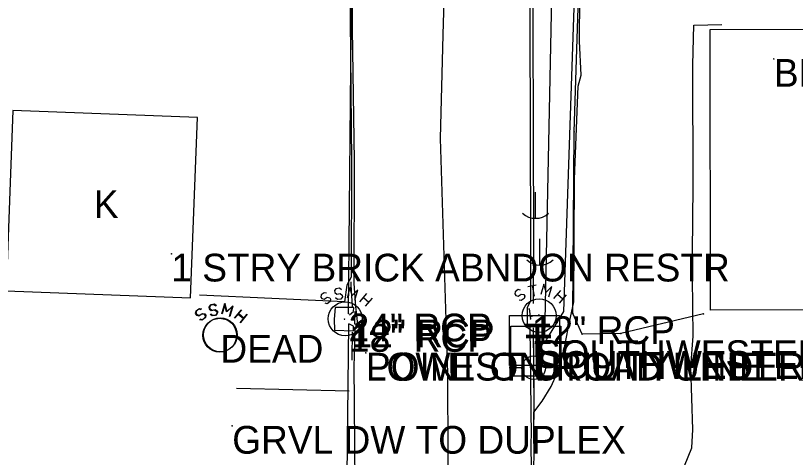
# Model space of a CAD drawing. Extents: x 1304270 to 1306561, y 1876019 to 1876752.
# Drawn here: x 1304900.2 to 1305040.8, y 1876244.8 to 1876324.4 of the extents above; entities that cross this region are included whole.
import ezdxf

# ---------------------------------------------------------------- set-up
doc = ezdxf.new("R2010")
doc.units = 0
for name, color, linetype in [('S_BUILDING', 7, 'Continuous'), ('S_BUILDING_ANNOT', 7, 'Continuous'), ('S_CATCH_BASIN', 7, 'Continuous'), ('S_CURB', 7, 'Continuous'), ('S_DRG_PT_SYM', 7, 'Continuous'), ('S_DRIVEWAY', 7, 'Continuous'), ('S_EDGE_CONCRETE', 7, 'Continuous'), ('S_EDGE_PAVEMENT', 7, 'Continuous'), ('S_ELECTRIC_UTILITIES_ANNOT', 7, 'Continuous'), ('S_FIBER_OPTIC_CABLE', 7, 'Continuous'), ('S_GAS_UTILITIES', 7, 'Continuous'), ('S_MSC_PT_SYM', 7, 'Continuous'), ('S_PARKING', 7, 'Continuous'), ('S_PAVEMENT_CROWN', 7, 'Continuous'), ('S_SANITARY_SEWER', 7, 'Continuous'), ('S_SANITARY_SEWER_ANNOT', 7, 'Continuous'), ('S_STORM_SEWER', 7, 'Continuous'), ('S_STORM_SEWER_ANNOT', 7, 'Continuous'), ('S_STR_PT_SYM', 7, 'Continuous'), ('S_SURVEY_TEXT_ANNOT', 7, 'Continuous'), ('S_TELEPHONE_UTILITIES', 7, 'Continuous'), ('S_TELEPHONE_UTILITIES_ANNOT', 7, 'Continuous'), ('S_UTILITY_POLE', 7, 'Continuous'), ('S_UTL_PT_SYM', 7, 'Continuous')]:
    doc.layers.add(name, color=color, linetype=linetype)

msp = doc.modelspace()

# ---------------------------------------------------------------- linework, layer by layer
at = {"layer": 'S_BUILDING'}
for points in [[(1305105.68, 1876271.43), (1305025.53, 1876271.29), (1305025.44, 1876321.83), (1305105.6, 1876321.96)], [(1304933.02, 1876306.02), (1304899.75, 1876307.28), (1304898.52, 1876274.75), (1304931.79, 1876273.49)]]:
    msp.add_lwpolyline(points, close=True, dxfattribs=at)
at = {"layer": 'S_CATCH_BASIN'}
for p, q in [((1304992.86, 1876271.51), (1304993.07, 1876269.69)), ((1304961.43, 1876268.81), (1304961.47, 1876270.98))]:
    msp.add_line(p, q, dxfattribs=at)
at = {"layer": 'S_CURB'}
for points in [[(1305002.33, 1876389.51), (1305000.99, 1876388.54), (1305000.03, 1876387.77), (1304998.78, 1876386.42), (1304997.67, 1876385.02), (1304996.71, 1876383.64), (1304995.81, 1876382.15), (1304995.25, 1876381.09), (1304994.76, 1876379.59), (1304994.22, 1876377.46), (1304993.74, 1876375.44), (1304993.56, 1876373.88), (1304993.51, 1876373.22), (1304993.31, 1876353.04), (1304993.41, 1876337.87), (1304993.52, 1876322.71), (1304993.56, 1876303.33), (1304993.6, 1876283.94), (1304993.53, 1876272.49)], [(1304960.7, 1876276.37), (1304960.7, 1876275.85), (1304960.93, 1876271.96)], [(1304960.9, 1876267.34), (1304960.85, 1876262.73), (1304960.87, 1876262.27)], [(1304993.57, 1876268.11), (1304993.67, 1876253.6), (1304993.62, 1876249.39)]]:
    msp.add_lwpolyline(points, dxfattribs=at)
at = {"layer": 'S_DRG_PT_SYM'}
for points in [[(1304992.86, 1876271.51), (1304992.86, 1876271.56), (1304992.86, 1876271.51), (1304992.81, 1876271.51), (1304992.86, 1876271.51), (1304992.86, 1876271.46), (1304992.86, 1876271.51), (1304992.91, 1876271.51)], [(1304961.47, 1876270.98), (1304961.47, 1876271.03), (1304961.47, 1876270.98), (1304961.42, 1876270.98), (1304961.47, 1876270.98), (1304961.47, 1876270.93), (1304961.47, 1876270.98), (1304961.52, 1876270.98)], [(1304961.43, 1876268.81), (1304961.43, 1876268.86), (1304961.43, 1876268.81), (1304961.38, 1876268.81), (1304961.43, 1876268.81), (1304961.43, 1876268.76), (1304961.43, 1876268.81), (1304961.48, 1876268.81)], [(1304993.07, 1876269.69), (1304993.07, 1876269.74), (1304993.07, 1876269.69), (1304993.02, 1876269.69), (1304993.07, 1876269.69), (1304993.07, 1876269.64), (1304993.07, 1876269.69), (1304993.12, 1876269.69)]]:
    msp.add_lwpolyline(points, dxfattribs=at)
at = {"layer": 'S_DRIVEWAY'}
msp.add_lwpolyline([(1304940.08, 1876257.24), (1304960.4, 1876256.74)], dxfattribs=at)
at = {"layer": 'S_EDGE_CONCRETE'}
for points in [[(1304961.23, 1876271.74), (1304957.86, 1876271.78), (1304957.69, 1876269.66), (1304957.73, 1876267.7), (1304961.17, 1876267.53), (1304961.14, 1876268.37), (1304960.3, 1876268.83)], [(1304960.46, 1876270.43), (1304961.16, 1876271.02), (1304961.23, 1876271.74)]]:
    msp.add_lwpolyline(points, dxfattribs=at)
at = {"layer": 'S_EDGE_PAVEMENT'}
for points in [[(1304992.58, 1876395.95), (1304992.67, 1876392.97), (1304992.89, 1876387.96), (1304993.12, 1876382.52), (1304992.95, 1876377.14), (1304992.83, 1876373.03), (1304992.83, 1876353.07), (1304992.88, 1876337.99), (1304992.93, 1876322.91), (1304993, 1876303.41), (1304993.07, 1876283.92), (1304993.07, 1876272.99), (1304992.49, 1876271.71), (1304992.46, 1876268.84), (1304992.98, 1876268.15), (1304993.15, 1876253.51), (1304993.2, 1876248.53), (1304993.13, 1876247.77), (1304993.23, 1876236.09), (1304993.14, 1876235.17), (1304993.16, 1876210.69)], [(1304961.3, 1876394.03), (1304961.33, 1876382.17), (1304961.23, 1876375.71), (1304961.22, 1876372.29), (1304960.99, 1876349.53), (1304961.06, 1876339.46), (1304960.95, 1876322), (1304961.28, 1876298.1), (1304961.25, 1876276.13), (1304961.53, 1876271.86), (1304961.62, 1876270.95), (1304961.87, 1876268.65), (1304961.43, 1876268.03), (1304961.3, 1876262.61), (1304961.21, 1876261.58), (1304961.4, 1876239.81), (1304961.49, 1876224.87), (1304961.47, 1876212.95)], [(1304993.51, 1876235.7), (1304993.73, 1876245.32), (1304993.66, 1876249.1), (1304993.69, 1876252.91), (1304995.2, 1876254.9), (1304996.77, 1876257.52), (1304997.79, 1876259.79), (1304999.07, 1876263.98), (1304999.95, 1876268.25), (1305000.86, 1876272.77), (1305001.03, 1876294.9), (1305001.64, 1876311.63), (1305002.2, 1876313.63), (1305001.91, 1876319.75), (1305001.96, 1876327.81)], [(1304994.06, 1876235.43), (1304999.1, 1876235.6), (1305007.63, 1876235.79), (1305013.63, 1876236.11), (1305016.38, 1876236.91), (1305020.82, 1876243.26), (1305022.14, 1876246.48), (1305022.34, 1876249.8), (1305021.98, 1876261.06), (1305022.37, 1876266.57), (1305022.29, 1876277.18), (1305022.28, 1876281.63), (1305022.38, 1876293.68), (1305022.35, 1876315.48), (1305022.51, 1876322.64), (1305027.56, 1876322.77)]]:
    msp.add_lwpolyline(points, dxfattribs=at)
at = {"layer": 'S_FIBER_OPTIC_CABLE'}
for p, q in [((1305001.98, 1876356.98), (1304999.02, 1876271.02)), ((1304997.12, 1876341.23), (1304995.58, 1876266.56)), ((1304999.02, 1876271.02), (1304995.98, 1876266.07))]:
    msp.add_line(p, q, dxfattribs=at)
at = {"layer": 'S_GAS_UTILITIES'}
for p, q in [((1305000.96, 1876303.41), (1305001.91, 1876334.61)), ((1305000.68, 1876270.67), (1305000.96, 1876303.41)), ((1305002.36, 1876266.93), (1305000.68, 1876270.67)), ((1305024.24, 1876270.6), (1305009.34, 1876267.08)), ((1305009.34, 1876267.08), (1305002.36, 1876266.93))]:
    msp.add_line(p, q, dxfattribs=at)
at = {"layer": 'S_MSC_PT_SYM'}
for points in [[(1304963.4, 1876263.6), (1304963.4, 1876263.65), (1304963.4, 1876263.6), (1304963.35, 1876263.6), (1304963.4, 1876263.6), (1304963.4, 1876263.55), (1304963.4, 1876263.6), (1304963.45, 1876263.6)], [(1304939.3, 1876250.42), (1304939.3, 1876250.47), (1304939.3, 1876250.42), (1304939.25, 1876250.42), (1304939.3, 1876250.42), (1304939.3, 1876250.37), (1304939.3, 1876250.42), (1304939.35, 1876250.42)]]:
    msp.add_lwpolyline(points, dxfattribs=at)
at = {"layer": 'S_PARKING'}
msp.add_lwpolyline([(1304960.55, 1876338.03), (1304960.57, 1876323.7), (1304960.68, 1876310.86), (1304960.8, 1876298.03), (1304960.72, 1876277.25), (1304959.98, 1876275.76), (1304959.52, 1876272.78), (1304946.45, 1876273.4), (1304933.38, 1876274.01)], dxfattribs=at)
at = {"layer": 'S_PAVEMENT_CROWN'}
msp.add_lwpolyline([(1304978.68, 1876396.09), (1304977.75, 1876372.31), (1304977.76, 1876355.96), (1304977.78, 1876339.61), (1304977.29, 1876320.92), (1304976.79, 1876302.23), (1304977.44, 1876281.07), (1304978.08, 1876259.92), (1304978.16, 1876244.79), (1304978.24, 1876229.66), (1304977.14, 1876211.47)], dxfattribs=at)
at = {"layer": 'S_SANITARY_SEWER'}
for p, q in [((1304955.88, 1876274.42), (1304955.34, 1876274.03)), ((1304956.31, 1876274.34), (1304955.88, 1876274.42)), ((1304962.31, 1876272.79), (1304963.55, 1876274.26)), ((1304955.34, 1876274.03), (1304955.26, 1876273.64)), ((1304955.26, 1876273.64), (1304955.45, 1876273.37)), ((1304955.45, 1876273.37), (1304955.88, 1876273.25)), ((1304955.88, 1876273.25), (1304956.42, 1876273.6)), ((1304956.42, 1876273.6), (1304956.89, 1876273.53)), ((1304956.97, 1876272.83), (1304956.42, 1876272.44)), ((1304956.89, 1876273.53), (1304957.04, 1876273.25)), ((1304957.04, 1876273.25), (1304956.97, 1876272.83)), ((1304962.97, 1876273.56), (1304963.94, 1876272.75)), ((1304964.52, 1876273.45), (1304963.28, 1876271.98)), ((1304933.25, 1876271.45), (1304932.71, 1876271.06)), ((1304933.37, 1876271.52), (1304932.83, 1876271.14)), ((1304933.68, 1876271.37), (1304933.25, 1876271.45)), ((1304933.8, 1876271.45), (1304933.37, 1876271.52)), ((1304939.8, 1876269.9), (1304941.04, 1876271.37)), ((1304956.42, 1876272.44), (1304956.04, 1876272.52)), ((1304932.71, 1876271.06), (1304932.63, 1876270.67)), ((1304932.63, 1876270.67), (1304932.83, 1876270.4)), ((1304932.83, 1876271.14), (1304932.75, 1876270.75)), ((1304932.75, 1876270.75), (1304932.94, 1876270.48)), ((1304932.83, 1876270.4), (1304933.25, 1876270.28)), ((1304932.94, 1876270.48), (1304933.37, 1876270.36)), ((1304933.25, 1876270.28), (1304933.8, 1876270.63)), ((1304933.37, 1876270.36), (1304933.91, 1876270.71)), ((1304933.8, 1876270.63), (1304934.26, 1876270.56)), ((1304933.91, 1876270.71), (1304934.38, 1876270.63)), ((1304934.46, 1876269.94), (1304933.91, 1876269.55)), ((1304934.26, 1876270.56), (1304934.42, 1876270.28)), ((1304934.42, 1876270.28), (1304934.34, 1876269.86)), ((1304934.38, 1876270.63), (1304934.53, 1876270.36)), ((1304934.53, 1876270.36), (1304934.46, 1876269.94)), ((1304939.69, 1876269.82), (1304940.93, 1876271.29)), ((1304940.34, 1876270.59), (1304941.31, 1876269.78)), ((1304940.46, 1876270.67), (1304941.43, 1876269.86)), ((1304941.89, 1876270.48), (1304940.65, 1876269.01)), ((1304942.01, 1876270.56), (1304940.77, 1876269.08)), ((1304933.8, 1876269.47), (1304933.41, 1876269.55)), ((1304933.91, 1876269.55), (1304933.53, 1876269.63)), ((1304934.34, 1876269.86), (1304933.8, 1876269.47))]:
    msp.add_line(p, q, dxfattribs=at)
for points in [[(1304958.98, 1876274.96), (1304958.63, 1876275.23), (1304957.97, 1876275.15), (1304957.74, 1876274.8), (1304957.78, 1876274.49), (1304958.13, 1876274.18), (1304958.75, 1876274.3), (1304959.14, 1876273.99), (1304959.17, 1876273.68), (1304958.9, 1876273.29), (1304958.28, 1876273.22), (1304957.93, 1876273.49)], [(1304961.42, 1876273.1), (1304961.96, 1876274.96), (1304960.92, 1876273.95), (1304960.53, 1876275.39), (1304959.99, 1876273.53)], [(1304936.35, 1876271.99), (1304936, 1876272.26), (1304935.35, 1876272.18), (1304935.11, 1876271.83), (1304935.15, 1876271.52), (1304935.5, 1876271.21), (1304936.12, 1876271.33), (1304936.51, 1876271.02), (1304936.55, 1876270.71), (1304936.28, 1876270.32), (1304935.66, 1876270.25), (1304935.31, 1876270.52)], [(1304936.47, 1876272.07), (1304936.12, 1876272.34), (1304935.46, 1876272.26), (1304935.23, 1876271.91), (1304935.27, 1876271.6), (1304935.62, 1876271.29), (1304936.24, 1876271.41), (1304936.63, 1876271.1), (1304936.66, 1876270.79), (1304936.39, 1876270.4), (1304935.77, 1876270.32), (1304935.42, 1876270.59)], [(1304938.79, 1876270.13), (1304939.34, 1876271.99), (1304938.29, 1876270.98), (1304937.9, 1876272.42), (1304937.36, 1876270.56)], [(1304938.91, 1876270.21), (1304939.45, 1876272.07), (1304938.41, 1876271.06), (1304938.02, 1876272.49), (1304937.48, 1876270.63)]]:
    msp.add_lwpolyline(points, dxfattribs=at)
for centre in [(1304959.67, 1876269.73), (1304937.04, 1876266.76), (1304937.16, 1876266.83)]:
    msp.add_circle(centre, 3.05, dxfattribs=at)
at = {"layer": 'S_STORM_SEWER'}
for p, q in [((1304960.28, 1876270.66), (1304961.45, 1876394.01)), ((1304992.6, 1876275.57), (1304994.11, 1876275.84)), ((1304993.37, 1876275.72), (1304993.72, 1876273.79)), ((1304990.31, 1876274.6), (1304990.23, 1876274.21)), ((1304990.23, 1876274.21), (1304990.43, 1876273.94)), ((1304990.85, 1876274.99), (1304990.31, 1876274.6)), ((1304991.28, 1876274.91), (1304990.85, 1876274.99)), ((1304990.85, 1876273.83), (1304991.4, 1876274.17)), ((1304991.4, 1876274.17), (1304991.86, 1876274.1)), ((1304997.29, 1876273.36), (1304998.53, 1876274.83)), ((1304990.43, 1876273.94), (1304990.85, 1876273.83)), ((1304991.4, 1876273.01), (1304991.01, 1876273.09)), ((1304991.94, 1876273.4), (1304991.4, 1876273.01)), ((1304991.86, 1876274.1), (1304992.02, 1876273.83)), ((1304992.02, 1876273.83), (1304991.94, 1876273.4)), ((1304997.95, 1876274.14), (1304998.91, 1876273.32)), ((1304999.5, 1876274.02), (1304998.26, 1876272.55)), ((1304959.89, 1876226.87), (1304960.34, 1876268.78))]:
    msp.add_line(p, q, dxfattribs=at)
msp.add_lwpolyline([(1304996.4, 1876273.67), (1304996.94, 1876275.53), (1304995.89, 1876274.52), (1304995.5, 1876275.96), (1304994.96, 1876274.1)], dxfattribs=at)
msp.add_circle((1304994.64, 1876270.3), 3.05, dxfattribs=at)
at = {"layer": 'S_STR_PT_SYM'}
for points in [[(1305036.95, 1876316.54), (1305036.95, 1876316.59), (1305036.95, 1876316.54), (1305036.9, 1876316.54), (1305036.95, 1876316.54), (1305036.95, 1876316.49), (1305036.95, 1876316.54), (1305037, 1876316.54)], [(1304928.32, 1876281.45), (1304928.32, 1876281.5), (1304928.32, 1876281.45), (1304928.27, 1876281.45), (1304928.32, 1876281.45), (1304928.32, 1876281.4), (1304928.32, 1876281.45), (1304928.37, 1876281.45)]]:
    msp.add_lwpolyline(points, dxfattribs=at)
at = {"layer": 'S_TELEPHONE_UTILITIES'}
for points in [[(1304989.31, 1876261.34), (1304989.31, 1876270.34), (1304998.31, 1876270.34), (1304998.31, 1876261.34)], [(1304989.52, 1876259.39), (1304989.52, 1876268.39), (1304998.52, 1876268.39), (1304998.52, 1876259.39)]]:
    msp.add_lwpolyline(points, close=True, dxfattribs=at)
at = {"layer": 'S_UTILITY_POLE'}
for p, q in [((1304993.91, 1876292.54), (1304993.91, 1876287.81)), ((1304994.72, 1876284.13), (1304994.72, 1876279.4)), ((1304993.65, 1876263.02), (1304993.65, 1876265.27)), ((1304991.55, 1876260.89), (1304989.23, 1876260.89)), ((1304993.72, 1876256.48), (1304993.72, 1876258.8))]:
    msp.add_line(p, q, dxfattribs=at)
msp.add_circle((1304993.65, 1876260.91), 2.13, dxfattribs=at)
for centre in [(1304993.98, 1876291.24), (1304994.78, 1876282.83)]:
    msp.add_arc(centre, 3.41, 226.3972, 313.6028, dxfattribs=at)
at = {"layer": 'S_UTL_PT_SYM'}
for points in [[(1305000.96, 1876303.41), (1305000.96, 1876303.46), (1305000.96, 1876303.41), (1305000.91, 1876303.41), (1305000.96, 1876303.41), (1305000.96, 1876303.36), (1305000.96, 1876303.41), (1305001.01, 1876303.41)], [(1304960.28, 1876270.66), (1304960.28, 1876270.71), (1304960.28, 1876270.66), (1304960.23, 1876270.66), (1304960.28, 1876270.66), (1304960.28, 1876270.61), (1304960.28, 1876270.66), (1304960.33, 1876270.66)], [(1304993.32, 1876270.18), (1304993.32, 1876270.23), (1304993.32, 1876270.18), (1304993.27, 1876270.18), (1304993.32, 1876270.18), (1304993.32, 1876270.13), (1304993.32, 1876270.18), (1304993.37, 1876270.18)], [(1304994.6, 1876270.44), (1304994.6, 1876270.49), (1304994.6, 1876270.44), (1304994.55, 1876270.44), (1304994.6, 1876270.44), (1304994.6, 1876270.39), (1304994.6, 1876270.44), (1304994.65, 1876270.44)], [(1304999.02, 1876271.02), (1304999.02, 1876271.07), (1304999.02, 1876271.02), (1304998.97, 1876271.02), (1304999.02, 1876271.02), (1304999.02, 1876270.97), (1304999.02, 1876271.02), (1304999.07, 1876271.02)], [(1305000.68, 1876270.67), (1305000.68, 1876270.72), (1305000.68, 1876270.67), (1305000.63, 1876270.67), (1305000.68, 1876270.67), (1305000.68, 1876270.62), (1305000.68, 1876270.67), (1305000.73, 1876270.67)], [(1305024.24, 1876270.6), (1305024.24, 1876270.65), (1305024.24, 1876270.6), (1305024.19, 1876270.6), (1305024.24, 1876270.6), (1305024.24, 1876270.55), (1305024.24, 1876270.6), (1305024.29, 1876270.6)], [(1304959.55, 1876269.68), (1304959.55, 1876269.73), (1304959.55, 1876269.68), (1304959.5, 1876269.68), (1304959.55, 1876269.68), (1304959.55, 1876269.63), (1304959.55, 1876269.68), (1304959.6, 1876269.68)], [(1304960.34, 1876268.78), (1304960.34, 1876268.83), (1304960.34, 1876268.78), (1304960.29, 1876268.78), (1304960.34, 1876268.78), (1304960.34, 1876268.73), (1304960.34, 1876268.78), (1304960.39, 1876268.78)], [(1304960.82, 1876269.58), (1304960.82, 1876269.63), (1304960.82, 1876269.58), (1304960.77, 1876269.58), (1304960.82, 1876269.58), (1304960.82, 1876269.53), (1304960.82, 1876269.58), (1304960.87, 1876269.58)], [(1305009.34, 1876267.08), (1305009.34, 1876267.13), (1305009.34, 1876267.08), (1305009.29, 1876267.08), (1305009.34, 1876267.08), (1305009.34, 1876267.03), (1305009.34, 1876267.08), (1305009.39, 1876267.08)], [(1304995.58, 1876266.56), (1304995.58, 1876266.61), (1304995.58, 1876266.56), (1304995.53, 1876266.56), (1304995.58, 1876266.56), (1304995.58, 1876266.51), (1304995.58, 1876266.56), (1304995.63, 1876266.56)], [(1304995.98, 1876266.07), (1304995.98, 1876266.12), (1304995.98, 1876266.07), (1304995.93, 1876266.07), (1304995.98, 1876266.07), (1304995.98, 1876266.02), (1304995.98, 1876266.07), (1304996.03, 1876266.07)], [(1305002.36, 1876266.93), (1305002.36, 1876266.98), (1305002.36, 1876266.93), (1305002.31, 1876266.93), (1305002.36, 1876266.93), (1305002.36, 1876266.88), (1305002.36, 1876266.93), (1305002.41, 1876266.93)], [(1304963.4, 1876263.6), (1304963.4, 1876263.65), (1304963.4, 1876263.6), (1304963.35, 1876263.6), (1304963.4, 1876263.6), (1304963.4, 1876263.55), (1304963.4, 1876263.6), (1304963.45, 1876263.6)]]:
    msp.add_lwpolyline(points, dxfattribs=at)

# ---------------------------------------------------------------- texts
at = {"layer": 'S_BUILDING_ANNOT'}
for s, p in [('BRICK AND MTL CORNER CROCERY AND MRKT', (1305036.95, 1876311.54)), ('K', (1304914.35, 1876287.89)), ('1 STRY BRICK ABNDON RESTR', (1304928.32, 1876276.45))]:
    msp.add_text(s, height=5, dxfattribs=at).set_placement(p)
at = {"layer": 'S_ELECTRIC_UTILITIES_ANNOT'}
msp.add_text('POINT ON ROAD UNDER LOWES', height=5, dxfattribs=at).set_placement((1304963.4, 1876258.6))
at = {"layer": 'S_SANITARY_SEWER_ANNOT'}
msp.add_text('DEAD', height=5, dxfattribs=at).set_placement((1304937.16, 1876261.83))
at = {"layer": 'S_STORM_SEWER_ANNOT'}
for s, p in [('24" RCP', (1304960.28, 1876265.66)), ('12" RCP', (1304993.32, 1876265.18)), ('18" RCP', (1304960.34, 1876263.78)), ('12" RCP', (1304960.82, 1876264.58))]:
    msp.add_text(s, height=5, dxfattribs=at).set_placement(p)
at = {"layer": 'S_SURVEY_TEXT_ANNOT'}
for s, p in [('LOWEST UTILITY LINE', (1304963.4, 1876258.6)), ('GRVL DW TO DUPLEX', (1304939.3, 1876245.42))]:
    msp.add_text(s, height=5, dxfattribs=at).set_placement(p)
at = {"layer": 'S_TELEPHONE_UTILITIES'}
for p in [(1304991.87, 1876262.84), (1304992.08, 1876260.89)]:
    msp.add_text('T', height=6, rotation=360, dxfattribs=at).set_placement(p)
at = {"layer": 'S_TELEPHONE_UTILITIES_ANNOT'}
for p in [(1304994.04, 1876260.85), (1304994.25, 1876258.9)]:
    msp.add_text('SOUTHWESTERN BELL', height=5, dxfattribs=at).set_placement(p)

doc.saveas('drawing.dxf')
